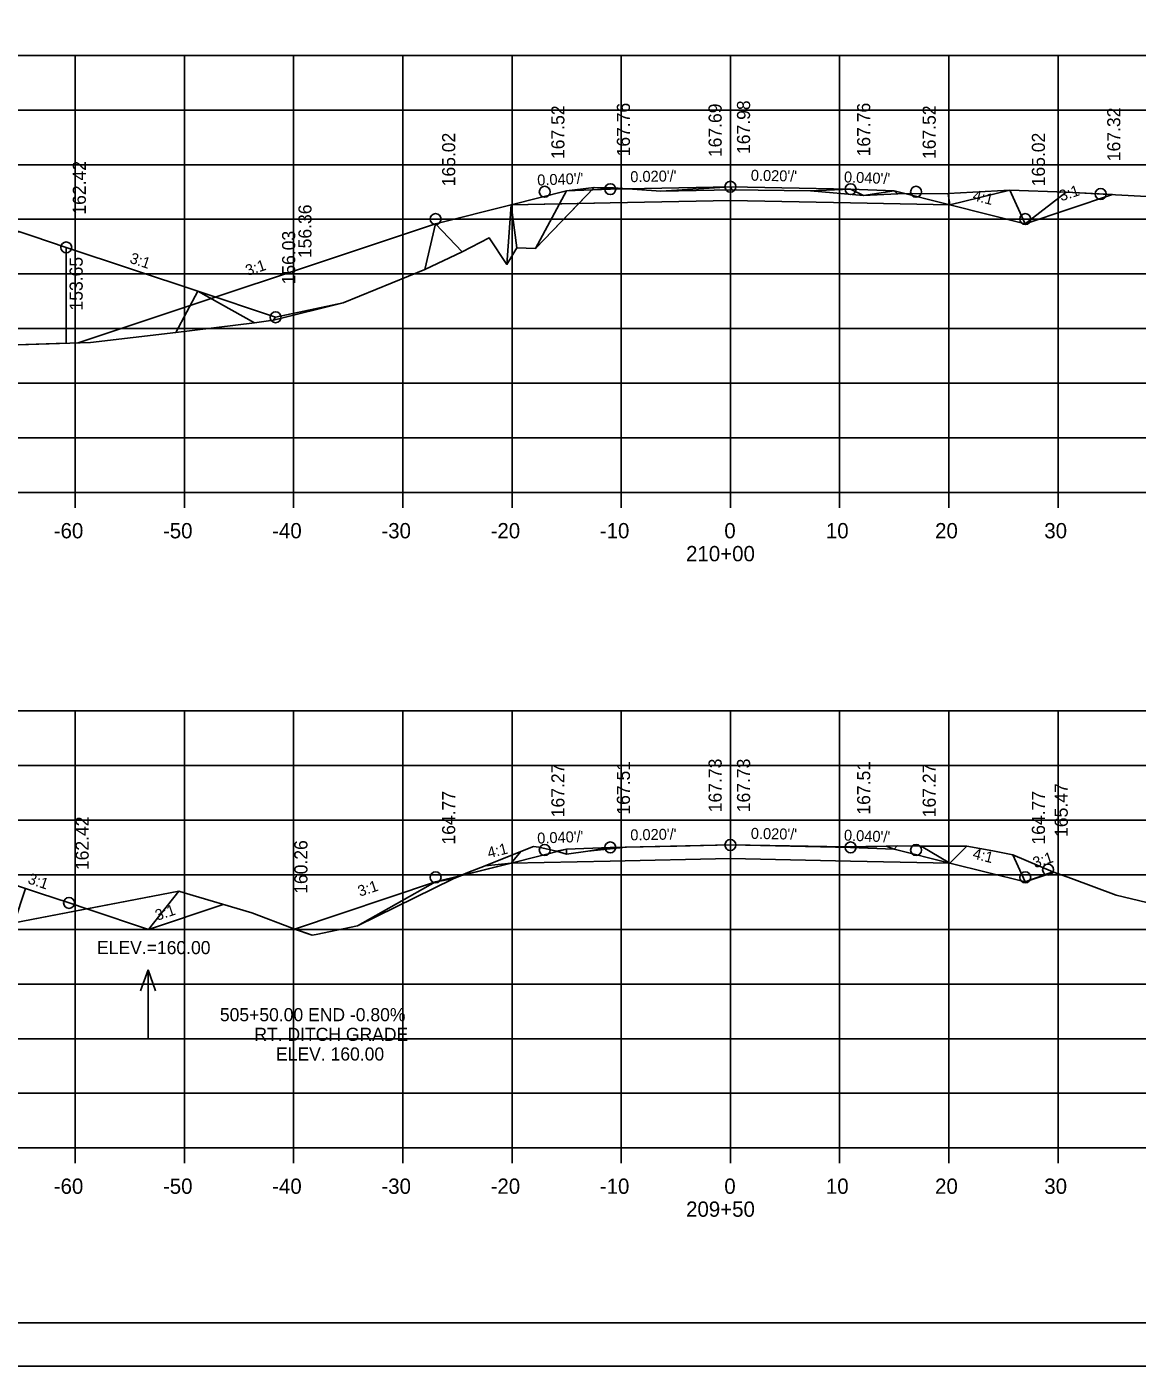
# Model space of a CAD drawing. Extents: x 1368503 to 1373085, y 379840 to 381833.
# Drawn here: x 1368608.6 to 1368710.3, y 380552.7 to 380675.3 of the extents above; entities that cross this region are included whole.
import ezdxf

# ---------------------------------------------------------------- set-up
doc = ezdxf.new("R2010")
doc.units = 0
for name, color, linetype in [('S_BRIDGE', 7, 'Continuous'), ('S_EDGE_PAVEMENT', 7, 'Continuous'), ('S_GRAVEL_ROAD', 7, 'Continuous'), ('S_MISC_BOUNDARY', 7, 'Continuous'), ('S_OBSCURES', 7, 'Continuous'), ('S_PHOTO_CENTERS', 7, 'Continuous'), ('S_PHOTO_NOTES', 7, 'Continuous'), ('S_RDW_PT_SYM', 7, 'Continuous'), ('S_SHOULDER', 7, 'Continuous'), ('S_STREAM_ANNOT', 7, 'Continuous'), ('S_TRAILS', 7, 'Continuous'), ('S_TRAILS_ANNOT', 7, 'Continuous'), ('S_TREE', 7, 'Continuous')]:
    doc.layers.add(name, color=color, linetype=linetype)

msp = doc.modelspace()

# ---------------------------------------------------------------- linework, layer by layer
at = {"layer": 'S_BRIDGE'}
msp.add_line((1368831.24, 380556.7), (1368515.06, 380556.7), dxfattribs=at)
at = {"layer": 'S_EDGE_PAVEMENT'}
for p, q in [((1368533.06, 380632.7), (1368813.06, 380632.7)), ((1368613.06, 380631.3), (1368613.06, 380632.7)), ((1368623.06, 380631.3), (1368623.06, 380632.7)), ((1368633.06, 380631.3), (1368633.06, 380632.7)), ((1368643.06, 380631.3), (1368643.06, 380632.7)), ((1368653.06, 380631.3), (1368653.06, 380632.7)), ((1368663.06, 380631.3), (1368663.06, 380632.7)), ((1368673.06, 380631.3), (1368673.06, 380632.7)), ((1368683.06, 380631.3), (1368683.06, 380632.7)), ((1368693.06, 380631.3), (1368693.06, 380632.7)), ((1368703.06, 380631.3), (1368703.06, 380632.7)), ((1368533.06, 380572.7), (1368813.06, 380572.7)), ((1368613.06, 380571.3), (1368613.06, 380572.7)), ((1368623.06, 380571.3), (1368623.06, 380572.7)), ((1368633.06, 380571.3), (1368633.06, 380572.7)), ((1368643.06, 380571.3), (1368643.06, 380572.7)), ((1368653.06, 380571.3), (1368653.06, 380572.7)), ((1368663.06, 380571.3), (1368663.06, 380572.7)), ((1368673.06, 380571.3), (1368673.06, 380572.7)), ((1368683.06, 380571.3), (1368683.06, 380572.7)), ((1368693.06, 380571.3), (1368693.06, 380572.7)), ((1368703.06, 380571.3), (1368703.06, 380572.7))]:
    msp.add_line(p, q, dxfattribs=at)
at = {"layer": 'S_GRAVEL_ROAD'}
for p, q in [((1368619.73, 380589), (1368619.03, 380587.08)), ((1368619.73, 380582.72), (1368619.73, 380589)), ((1368619.73, 380589), (1368620.43, 380587.08))]:
    msp.add_line(p, q, dxfattribs=at)
at = {"layer": 'S_MISC_BOUNDARY'}
for points in [[(1368600.25, 380645.98), (1368614.45, 380646.43), (1368622.28, 380647.35), (1368629.47, 380648.24), (1368630.76, 380648.41), (1368631.22, 380648.46), (1368631.22, 380648.46), (1368631.22, 380648.46), (1368631.22, 380648.46), (1368637.61, 380650.06), (1368645.09, 380653.1), (1368648.5, 380654.73), (1368650.96, 380656.02), (1368652.6, 380653.57), (1368653.51, 380655.09), (1368655.22, 380655.04), (1368660.58, 380660.62), (1368662.35, 380660.57), (1368666.68, 380660.28), (1368673.19, 380660.39), (1368680.4, 380660.3), (1368685.24, 380659.88), (1368688.36, 380660.02), (1368692.99, 380660.07), (1368698.64, 380660.37), (1368703.79, 380660.19), (1368717.95, 380659.43)], [(1368607.46, 380593.31), (1368622.55, 380596.19), (1368623.04, 380596.04), (1368629.23, 380594.21), (1368632.92, 380592.81), (1368634.75, 380592.18), (1368635.13, 380592.25), (1368638.9, 380593.02), (1368647.66, 380597.33), (1368649.01, 380597.92), (1368650.6, 380598.53), (1368653.88, 380599.83), (1368655.04, 380600.3), (1368655.53, 380600.23), (1368657.14, 380599.86), (1368658.06, 380599.6), (1368660, 380599.85), (1368663.52, 380600.22), (1368668.14, 380600.33), (1368673.07, 380600.43), (1368678.48, 380600.34), (1368683.6, 380600.25), (1368687.31, 380600.32), (1368688.34, 380600.34), (1368690.51, 380600.31), (1368694.71, 380600.31), (1368697.09, 380599.89), (1368698.93, 380599.54), (1368702.59, 380597.98), (1368704.3, 380597.37), (1368708.38, 380595.85), (1368711.19, 380595.17)]]:
    msp.add_lwpolyline(points, dxfattribs=at)
at = {"layer": 'S_OBSCURES'}
for points in [[(1368693.15, 380659.03), (1368684.06, 380659.21), (1368673.06, 380659.43), (1368662.06, 380659.21), (1368652.97, 380659.03)], [(1368693.15, 380598.78), (1368684.06, 380598.96), (1368673.06, 380599.18), (1368662.06, 380598.96), (1368652.97, 380598.78)]]:
    msp.add_lwpolyline(points, dxfattribs=at)
at = {"layer": 'S_PHOTO_CENTERS'}
for p, q in [((1368533.06, 380672.7), (1368813.06, 380672.7)), ((1368613.06, 380632.7), (1368613.06, 380672.7)), ((1368623.06, 380632.7), (1368623.06, 380672.7)), ((1368633.06, 380632.7), (1368633.06, 380672.7)), ((1368643.06, 380632.7), (1368643.06, 380672.7)), ((1368653.06, 380632.7), (1368653.06, 380672.7)), ((1368663.06, 380632.7), (1368663.06, 380672.7)), ((1368673.06, 380632.7), (1368673.06, 380672.7)), ((1368683.06, 380632.7), (1368683.06, 380672.7)), ((1368693.06, 380632.7), (1368693.06, 380672.7)), ((1368703.06, 380632.7), (1368703.06, 380672.7)), ((1368533.06, 380667.7), (1368813.06, 380667.7)), ((1368533.06, 380662.7), (1368813.06, 380662.7)), ((1368533.06, 380657.7), (1368813.06, 380657.7)), ((1368533.06, 380652.7), (1368813.06, 380652.7)), ((1368533.06, 380647.7), (1368813.06, 380647.7)), ((1368533.06, 380642.7), (1368813.06, 380642.7)), ((1368533.06, 380637.7), (1368813.06, 380637.7)), ((1368533.06, 380632.7), (1368813.06, 380632.7)), ((1368533.06, 380612.7), (1368813.06, 380612.7)), ((1368613.06, 380572.7), (1368613.06, 380612.7)), ((1368623.06, 380572.7), (1368623.06, 380612.7)), ((1368633.06, 380572.7), (1368633.06, 380612.7)), ((1368643.06, 380572.7), (1368643.06, 380612.7)), ((1368653.06, 380572.7), (1368653.06, 380612.7)), ((1368663.06, 380572.7), (1368663.06, 380612.7)), ((1368673.06, 380572.7), (1368673.06, 380612.7)), ((1368683.06, 380572.7), (1368683.06, 380612.7)), ((1368693.06, 380572.7), (1368693.06, 380612.7)), ((1368703.06, 380572.7), (1368703.06, 380612.7)), ((1368533.06, 380607.7), (1368813.06, 380607.7)), ((1368533.06, 380602.7), (1368813.06, 380602.7)), ((1368533.06, 380597.7), (1368813.06, 380597.7)), ((1368533.06, 380592.7), (1368813.06, 380592.7)), ((1368533.06, 380587.7), (1368813.06, 380587.7)), ((1368533.06, 380582.7), (1368813.06, 380582.7)), ((1368533.06, 380577.7), (1368813.06, 380577.7)), ((1368533.06, 380572.7), (1368813.06, 380572.7))]:
    msp.add_line(p, q, dxfattribs=at)
at = {"layer": 'S_PHOTO_NOTES'}
msp.add_line((1368502.66, 380552.73), (1368835.99, 380552.73), dxfattribs=at)
for points in [[(1368502.65, 380766.06), (1368835.99, 380766.06), (1368835.99, 380552.72), (1368502.65, 380552.72)], [(1368748.98, 380762.16), (1368748.98, 380752.28), (1368784.71, 380752.28), (1368784.71, 380749.36), (1368807.91, 380749.36), (1368807.91, 380725.03), (1368831.24, 380725.03), (1368831.24, 380556.7), (1368515.06, 380556.7), (1368515.06, 380762.16)], [(1368655.22, 380655.04), (1368660.58, 380660.62), (1368658.06, 380660.3)], [(1368659.17, 380659.15), (1368660.58, 380660.62), (1368662.35, 380660.57), (1368666.68, 380660.28), (1368673.19, 380660.39), (1368680.4, 380660.3), (1368685.24, 380659.88), (1368688.36, 380660.02), (1368692.99, 380660.07), (1368698.64, 380660.37), (1368703.79, 380660.19), (1368708.04, 380659.96), (1368700.06, 380657.3), (1368693.15, 380659.03), (1368684.06, 380659.21), (1368673.06, 380659.43), (1368662.06, 380659.21)], [(1368660.58, 380660.62), (1368662.35, 380660.57), (1368662.06, 380660.46)], [(1368666.68, 380660.28), (1368673.19, 380660.39), (1368673.06, 380660.68)], [(1368680.4, 380660.3), (1368685.24, 380659.88), (1368684.06, 380660.46)], [(1368685.24, 380659.88), (1368688.36, 380660.02), (1368688.06, 380660.3)], [(1368692.99, 380660.07), (1368698.64, 380660.37), (1368693.15, 380659.03)], [(1368698.64, 380660.37), (1368703.79, 380660.19), (1368700.06, 380657.3)], [(1368613.34, 380646.39), (1368614.45, 380646.43), (1368622.28, 380647.35), (1368629.47, 380648.24), (1368630.76, 380648.41), (1368631.22, 380648.46), (1368631.22, 380648.46), (1368631.22, 380648.46), (1368631.22, 380648.46), (1368637.61, 380650.06), (1368645.09, 380653.1), (1368648.5, 380654.73), (1368650.96, 380656.02), (1368652.6, 380653.57), (1368653.51, 380655.09), (1368655.22, 380655.04), (1368659.17, 380659.15), (1368652.97, 380659.03), (1368646.06, 380657.3)], [(1368652.6, 380653.57), (1368653.51, 380655.09), (1368652.97, 380659.03)], [(1368600.25, 380645.98), (1368612.24, 380646.36), (1368612.24, 380655.13), (1368609.17, 380656.15), (1368608.1, 380656.51), (1368602.24, 380656.62), (1368602.03, 380656.63)], [(1368645.09, 380653.1), (1368648.5, 380654.73), (1368646.06, 380657.3)], [(1368622.28, 380647.35), (1368629.47, 380648.24), (1368624.3, 380651.11)], [(1368631.22, 380648.46), (1368637.61, 380650.06), (1368631.41, 380648.74)], [(1368648.33, 380597.62), (1368649.01, 380597.92), (1368650.6, 380598.53), (1368653.88, 380599.83), (1368655.04, 380600.3), (1368655.53, 380600.23), (1368657.14, 380599.86), (1368658.06, 380599.6), (1368660, 380599.85), (1368663.52, 380600.22), (1368668.14, 380600.33), (1368673.07, 380600.43), (1368678.48, 380600.34), (1368683.6, 380600.25), (1368687.31, 380600.32), (1368688.34, 380600.34), (1368690.51, 380600.31), (1368694.71, 380600.31), (1368697.09, 380599.89), (1368698.93, 380599.54), (1368702.59, 380597.98), (1368702.71, 380597.94), (1368700.06, 380597.05), (1368693.15, 380598.78), (1368684.06, 380598.96), (1368673.06, 380599.18), (1368662.06, 380598.96), (1368652.97, 380598.78)], [(1368657.14, 380599.86), (1368658.06, 380599.6), (1368658.06, 380600.05)], [(1368660, 380599.85), (1368663.52, 380600.22), (1368662.06, 380600.21)], [(1368683.6, 380600.25), (1368687.31, 380600.32), (1368684.06, 380600.21)], [(1368687.31, 380600.32), (1368688.34, 380600.34), (1368688.06, 380600.05)], [(1368690.51, 380600.31), (1368694.71, 380600.31), (1368693.15, 380598.78)], [(1368650.6, 380598.53), (1368653.88, 380599.83), (1368652.97, 380598.78)], [(1368698.93, 380599.54), (1368702.59, 380597.98), (1368700.06, 380597.05)], [(1368633.13, 380592.74), (1368634.75, 380592.18), (1368635.13, 380592.25), (1368638.9, 380593.02), (1368647.66, 380597.33), (1368648.33, 380597.62), (1368646.06, 380597.05)], [(1368607.46, 380593.31), (1368614.13, 380594.58), (1368612.5, 380595.13), (1368609.79, 380596.03), (1368608.5, 380596.46)], [(1368638.9, 380593.02), (1368647.66, 380597.33), (1368646.06, 380597.05)], [(1368614.13, 380594.58), (1368622.55, 380596.19), (1368619.77, 380592.7), (1368614.3, 380594.53)]]:
    msp.add_lwpolyline(points, close=True, dxfattribs=at)
for centre in [(1368656.06, 380660.22), (1368662.06, 380660.46), (1368673.06, 380660.68), (1368684.06, 380660.46), (1368690.06, 380660.22), (1368706.96, 380660.02), (1368646.06, 380657.72), (1368700.06, 380657.72), (1368612.24, 380655.13), (1368631.41, 380648.74), (1368656.06, 380599.97), (1368662.06, 380600.21), (1368673.06, 380600.43), (1368684.06, 380600.21), (1368690.06, 380599.97), (1368646.06, 380597.47), (1368700.06, 380597.47), (1368702.15, 380598.17), (1368612.5, 380595.13)]:
    msp.add_circle(centre, 0.5, dxfattribs=at)
at = {"layer": 'S_STREAM_ANNOT'}
for points in [[(1368613.34, 380646.39), (1368646.06, 380657.3), (1368652.97, 380659.03), (1368658.06, 380660.3), (1368662.06, 380660.46), (1368673.06, 380660.68), (1368684.06, 380660.46), (1368688.06, 380660.3), (1368693.15, 380659.03), (1368700.06, 380657.3), (1368708.04, 380659.96)], [(1368541.42, 380655.41), (1368553.09, 380651.52), (1368556.87, 380650.26), (1368568.61, 380654.17), (1368572.24, 380655.38), (1368575.12, 380656.34), (1368576.14, 380656.68), (1368579.22, 380657.71), (1368580.24, 380658.05), (1368581.73, 380658.04), (1368582.24, 380658.05), (1368584.79, 380658.1), (1368592.24, 380658.07), (1368594.8, 380658.02), (1368602.24, 380657.87), (1368603.72, 380657.81), (1368604.24, 380657.79), (1368607.11, 380656.84), (1368608.1, 380656.51), (1368609.17, 380656.15), (1368612.24, 380655.13), (1368624.3, 380651.11), (1368631.41, 380648.74)], [(1368633.13, 380592.74), (1368646.06, 380597.05), (1368652.97, 380598.78), (1368658.06, 380600.05), (1368662.06, 380600.21), (1368673.06, 380600.43), (1368684.06, 380600.21), (1368688.06, 380600.05), (1368693.15, 380598.78), (1368700.06, 380597.05), (1368702.71, 380597.94)], [(1368543.58, 380586.17), (1368557.5, 380590.81), (1368572.5, 380595.81), (1368575.01, 380596.65), (1368576.2, 380597.05), (1368579.15, 380598.03), (1368580.5, 380598.48), (1368581.86, 380598.43), (1368582.5, 380598.42), (1368585.67, 380598.36), (1368592.5, 380598.15), (1368595.65, 380598.09), (1368602.5, 380597.87), (1368603.87, 380597.82), (1368604.5, 380597.79), (1368605.71, 380597.39), (1368608.5, 380596.46), (1368609.79, 380596.03), (1368612.5, 380595.13), (1368614.3, 380594.53), (1368619.77, 380592.7), (1368626.61, 380594.99)]]:
    msp.add_lwpolyline(points, dxfattribs=at)
at = {"layer": 'S_TREE'}
msp.add_line((1368619.77, 380592.7), (1368626.61, 380594.99), dxfattribs=at)

# ---------------------------------------------------------------- texts
at = {"layer": 'S_GRAVEL_ROAD'}
for s, p in [('ELEV.=160.00', (1368615.06, 380590.44)), ('505+50.00 END -0.80%', (1368626.31, 380584.3)), ('RT. DITCH GRADE', (1368629.47, 380582.5)), ('ELEV. 160.00', (1368631.45, 380580.7))]:
    msp.add_text(s, height=1.2, dxfattribs=at).set_placement(p)
at = {"layer": 'S_RDW_PT_SYM'}
for s, rotation, p in [("0.040'/'", 2.2906, (1368655.39, 380660.79)), ("0.040'/'", 2.2906, (1368655.39, 380660.79)), ("0.020'/'", 1.1458, (1368663.9, 380661.1)), ("0.020'/'", 1.1458, (1368663.9, 380661.1)), ("0.020'/'", 358.8542, (1368674.92, 380661.24)), ("0.020'/'", 358.8542, (1368674.92, 380661.24)), ("0.040'/'", 357.7094, (1368683.44, 380661.09)), ("0.040'/'", 357.7094, (1368683.44, 380661.09)), ('4:1', 345.9638, (1368695.18, 380659.45)), ('4:1', 345.9638, (1368695.18, 380659.45)), ('3:1', 18.4332, (1368703.35, 380659.34)), ('3:1', 18.4332, (1368703.35, 380659.34)), ('3:1', 341.5664, (1368617.98, 380653.74)), ('3:1', 18.4332, (1368628.85, 380652.51)), ('3:1', 18.4332, (1368628.85, 380652.51)), ("0.040'/'", 2.2906, (1368655.39, 380600.55)), ("0.040'/'", 2.2906, (1368655.39, 380600.55)), ("0.020'/'", 1.1458, (1368663.9, 380600.85)), ("0.020'/'", 1.1458, (1368663.9, 380600.85)), ("0.020'/'", 358.8542, (1368674.92, 380601)), ("0.020'/'", 358.8542, (1368674.92, 380601)), ("0.040'/'", 357.7094, (1368683.44, 380600.84)), ("0.040'/'", 357.7094, (1368683.44, 380600.84)), ('4:1', 14.0362, (1368650.94, 380599.21)), ('4:1', 14.0362, (1368650.94, 380599.21)), ('4:1', 345.9638, (1368695.18, 380599.21)), ('4:1', 345.9638, (1368695.18, 380599.21)), ('3:1', 18.4332, (1368700.94, 380598.3)), ('3:1', 18.4332, (1368700.94, 380598.3)), ('3:1', 341.5653, (1368608.65, 380596.94)), ('3:1', 18.4332, (1368639.13, 380595.69)), ('3:1', 18.4332, (1368639.13, 380595.69)), ('3:1', 18.4332, (1368620.57, 380593.49))]:
    msp.add_text(s, height=1, rotation=rotation, dxfattribs=at).set_placement(p)
at = {"layer": 'S_SHOULDER'}
for s, p in [('167.52', (1368657.86, 380663.22)), ('167.76', (1368663.86, 380663.46)), ('167.98', (1368674.86, 380663.68)), ('167.76', (1368685.86, 380663.46)), ('167.52', (1368691.86, 380663.22)), ('167.32', (1368708.76, 380663.02)), ('165.02', (1368647.86, 380660.72)), ('165.02', (1368701.86, 380660.72)), ('162.42', (1368614.04, 380658.13)), ('156.36', (1368634.7, 380654.15)), ('156.03', (1368633.21, 380651.74)), ('153.65', (1368613.75, 380649.35)), ('167.27', (1368657.86, 380602.97)), ('167.51', (1368663.86, 380603.21)), ('167.73', (1368674.86, 380603.43)), ('167.51', (1368685.86, 380603.21)), ('167.27', (1368691.86, 380602.97)), ('164.77', (1368647.86, 380600.47)), ('164.77', (1368701.86, 380600.47)), ('165.47', (1368703.95, 380601.17)), ('162.42', (1368614.3, 380598.13)), ('160.26', (1368634.33, 380595.96))]:
    msp.add_text(s, height=1.2, rotation=90, dxfattribs=at).set_placement(p)
at = {"layer": 'S_TRAILS'}
for s, p in [('-60', (1368611.1, 380628.5)), ('-50', (1368621.1, 380628.5)), ('-40', (1368631.1, 380628.5)), ('-30', (1368641.1, 380628.5)), ('-20', (1368651.1, 380628.5)), ('-10', (1368661.1, 380628.5)), ('0', (1368672.5, 380628.5)), ('10', (1368681.8, 380628.5)), ('20', (1368691.8, 380628.5)), ('30', (1368701.8, 380628.5)), ('210+00', (1368669, 380626.4)), ('-60', (1368611.1, 380568.5)), ('-50', (1368621.1, 380568.5)), ('-40', (1368631.1, 380568.5)), ('-30', (1368641.1, 380568.5)), ('-20', (1368651.1, 380568.5)), ('-10', (1368661.1, 380568.5)), ('0', (1368672.5, 380568.5)), ('10', (1368681.8, 380568.5)), ('20', (1368691.8, 380568.5)), ('30', (1368701.8, 380568.5)), ('209+50', (1368669, 380566.4))]:
    msp.add_text(s, height=1.4, dxfattribs=at).set_placement(p)
at = {"layer": 'S_TRAILS_ANNOT'}
for s, p in [('167.69', (1368672.26, 380663.39)), ('167.73', (1368672.26, 380603.43))]:
    msp.add_text(s, height=1.2, rotation=90, dxfattribs=at).set_placement(p)

doc.saveas('drawing.dxf')
